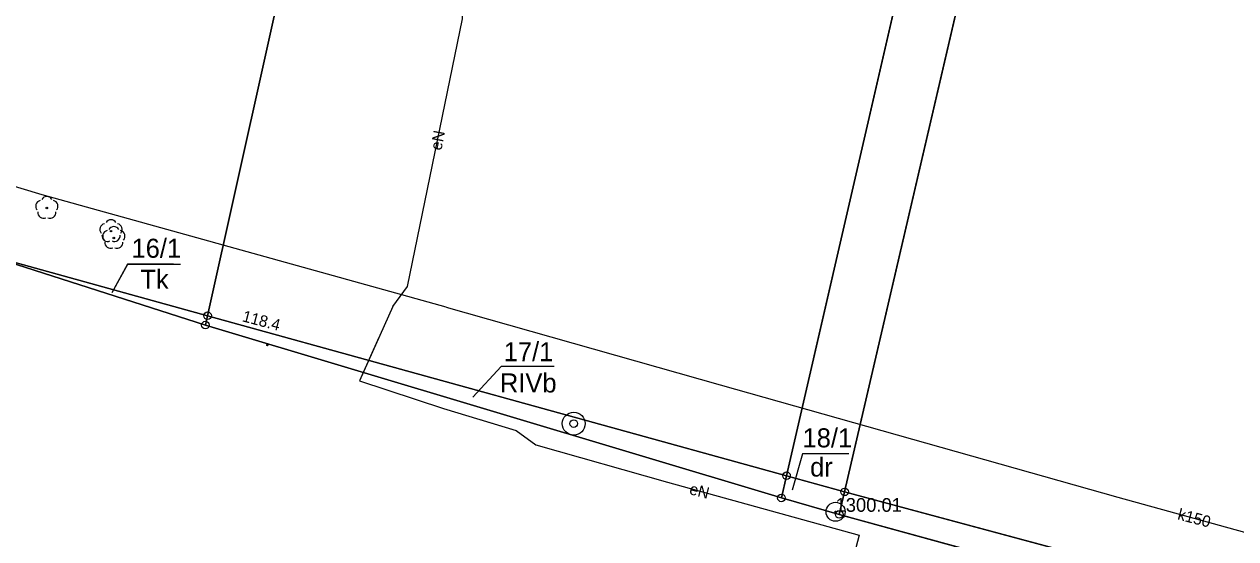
# Model space of a CAD drawing. Extents: x 6424617 to 6425697, y 5665845 to 5667190.
# Drawn here: x 6424782.2 to 6424861.7, y 5666055.5 to 5666089.2 of the extents above; entities that cross this region are included whole.
import ezdxf

# ---------------------------------------------------------------- set-up
doc = ezdxf.new("R2010")
doc.units = 0
for name, color, linetype in [('Warstwa 1', 7, 'Continuous'), ('Warstwa 10', 7, 'Continuous'), ('Warstwa 11', 7, 'Continuous'), ('Warstwa 12', 7, 'Continuous'), ('Warstwa 13', 7, 'Continuous'), ('Warstwa 15', 7, 'Continuous'), ('Warstwa 2', 7, 'Continuous'), ('Warstwa 3', 7, 'Continuous'), ('Warstwa 30', 7, 'Continuous'), ('Warstwa 4', 7, 'Continuous'), ('Warstwa 6', 7, 'Continuous'), ('Warstwa 8', 7, 'Continuous')]:
    doc.layers.add(name, color=color, linetype=linetype)

msp = doc.modelspace()

# ---------------------------------------------------------------- linework, layer by layer
at = {"layer": 'Warstwa 1'}
for p, q in [((6424832.261, 5666059.596), (6424844.483, 5666112.623)), ((6424832.261, 5666059.596), (6424844.483, 5666112.623)), ((6424836.069, 5666058.54), (6424848.434, 5666111.775)), ((6424836.069, 5666058.54), (6424848.434, 5666111.775)), ((6424794.275, 5666070.095), (6424801.04, 5666100.505)), ((6424794.275, 5666070.095), (6424801.04, 5666100.505)), ((6424779.333, 5666074.236), (6424794.275, 5666070.095)), ((6424779.333, 5666074.236), (6424794.275, 5666070.095)), ((6424779.333, 5666074.236), (6424794.137, 5666069.487)), ((6424779.333, 5666074.236), (6424794.137, 5666069.487)), ((6424794.137, 5666069.487), (6424794.275, 5666070.095)), ((6424794.137, 5666069.487), (6424794.275, 5666070.095)), ((6424794.275, 5666070.095), (6424832.261, 5666059.596)), ((6424794.275, 5666070.095), (6424832.261, 5666059.596)), ((6424794.137, 5666069.487), (6424831.924, 5666058.14)), ((6424794.137, 5666069.487), (6424831.924, 5666058.14)), ((6424831.924, 5666058.14), (6424832.261, 5666059.596)), ((6424831.924, 5666058.14), (6424832.261, 5666059.596)), ((6424832.261, 5666059.596), (6424836.069, 5666058.54)), ((6424832.261, 5666059.596), (6424836.069, 5666058.54)), ((6424831.924, 5666058.14), (6424835.721, 5666057.054)), ((6424831.924, 5666058.14), (6424835.721, 5666057.054)), ((6424835.721, 5666057.054), (6424836.069, 5666058.54)), ((6424835.721, 5666057.054), (6424836.069, 5666058.54)), ((6424836.069, 5666058.54), (6424894.579, 5666042.817)), ((6424836.069, 5666058.54), (6424894.579, 5666042.817)), ((6424835.721, 5666057.054), (6424969.125, 5666020.47)), ((6424835.721, 5666057.054), (6424969.125, 5666020.47))]:
    msp.add_line(p, q, dxfattribs=at)
at = {"layer": 'Warstwa 10'}
for centre in [(6424794.275, 5666070.095), (6424794.137, 5666069.487), (6424794.137, 5666069.487), (6424832.261, 5666059.596), (6424836.069, 5666058.54), (6424831.924, 5666058.14), (6424831.924, 5666058.14), (6424835.721, 5666057.054), (6424835.721, 5666057.054)]:
    msp.add_circle(centre, 0.25, dxfattribs=at)
at = {"layer": 'Warstwa 11'}
for centre in [(6424783.729, 5666077.173), (6424787.941, 5666075.652), (6424788.126, 5666075.2)]:
    msp.add_circle(centre, 0.05, dxfattribs=at)
for centre, start, end in [((6424783.729, 5666077.548), 30.14713, 149.85287), ((6424783.372, 5666077.289), 102.14713, 221.85287), ((6424784.086, 5666077.289), 318.14713, 77.85287), ((6424783.509, 5666076.87), 174.14713, 293.85287), ((6424783.949, 5666076.87), 246.14713, 5.85287), ((6424787.941, 5666076.027), 30.14713, 149.85287), ((6424787.584, 5666075.768), 102.14713, 221.85287), ((6424787.769, 5666075.316), 102.14713, 221.85287), ((6424788.126, 5666075.575), 30.14713, 149.85287), ((6424788.298, 5666075.768), 318.14713, 77.85287), ((6424788.483, 5666075.316), 318.14713, 77.85287), ((6424787.721, 5666075.349), 174.14713, 293.85287), ((6424787.906, 5666074.897), 174.14713, 293.85287), ((6424788.161, 5666075.349), 246.14713, 5.85287), ((6424788.346, 5666074.897), 246.14713, 5.85287)]:
    msp.add_arc(centre, 0.375, start, end, dxfattribs=at)
at = {"layer": 'Warstwa 12'}
for points in [[(6424809.935, 5666070.656), (6424783.427, 5666078.025), (6424764.456, 5666083.749), (6424739.613, 5666091.527), (6424715.65, 5666099.074), (6424704.282, 5666102.608), (6424685.892, 5666108.173), (6424678.724, 5666110.413), (6424672.982, 5666122.702), (6424666.592, 5666122.274)], [(6424806.432, 5666070.699), (6424807.399, 5666072.021), (6424811.008, 5666089.581), (6424811.307, 5666096.789)], [(6424806.432, 5666070.699), (6424804.245, 5666065.824), (6424809.759, 5666064.004), (6424814.529, 5666062.559), (6424815.808, 5666061.619), (6424824.451, 5666059.181), (6424837.021, 5666055.705), (6424833.173, 5666041.029), (6424830.852, 5666030.123), (6424832.02, 5666026.17), (6424832.44, 5666024.14), (6424839.63, 5666022.65), (6424842.32, 5666021.91), (6424840.72, 5666014.14), (6424839.536, 5666008.446)], [(6424809.935, 5666070.656), (6424827.909, 5666065.556), (6424854.005, 5666058.199), (6424902.191, 5666044.874)]]:
    msp.add_lwpolyline(points, dxfattribs=at)
at = {"layer": 'Warstwa 13'}
msp.add_circle((6424798.199, 5666068.179), 0.045, dxfattribs=at)
at = {"layer": 'Warstwa 15'}
for points in [[(6424792.041, 5666073.474), (6424789.03, 5666073.474), (6424788.002, 5666071.612)], [(6424816.487, 5666066.764), (6424813.535, 5666066.764), (6424811.681, 5666064.755)], [(6424836.35, 5666061.029), (6424833.3, 5666061.029), (6424832.631, 5666058.648)]]:
    msp.add_lwpolyline(points, dxfattribs=at)
at = {"layer": 'Warstwa 2'}
for points in [[(6424792.503, 5666073.469), (6424789.03, 5666073.469), (6424788.002, 5666071.612)], [(6424817.007, 5666066.758), (6424813.535, 5666066.758), (6424811.681, 5666064.755)], [(6424836.35, 5666061.029), (6424833.3, 5666061.029), (6424832.631, 5666058.648)]]:
    msp.add_lwpolyline(points, dxfattribs=at)
at = {"layer": 'Warstwa 3'}
for radius in [0.625, 0.045]:
    msp.add_circle((6424835.48, 5666057.23), radius, dxfattribs=at)
at = {"layer": 'Warstwa 30'}
for radius in [0.75, 0.25]:
    msp.add_circle((6424818.302, 5666063.018), radius, dxfattribs=at)
at = {"layer": 'Warstwa 6'}
for points in [[(6424854.405, 5666155.706), (6424844.483, 5666112.623), (6424832.261, 5666059.596), (6424836.069, 5666058.54), (6424848.434, 5666111.775), (6424858.372, 5666154.628), (6424860.068, 5666161.718), (6424874.142, 5666220.733), (6424875.3, 5666225.6), (6424883.591, 5666260.362), (6424885.665, 5666269.038), (6424887.972, 5666278.68), (6424890.615, 5666291.389), (6424891.59, 5666295.947), (6424888.255, 5666297.218), (6424884.032, 5666279.588), (6424881.866, 5666269.974)], [(6424995.086, 5666125.706), (6424929.132, 5666143.293), (6424860.068, 5666161.718), (6424858.372, 5666154.628), (6424848.434, 5666111.775), (6424836.069, 5666058.54), (6424900.676, 5666041.179), (6424958.467, 5666024.929), (6424969.493, 5666021.946)], [(6424854.405, 5666155.706), (6424811.635, 5666146.942), (6424805.696, 5666121.432), (6424794.275, 5666070.095), (6424832.261, 5666059.596), (6424844.483, 5666112.623)], [(6424722.032, 5666092.611), (6424752.267, 5666082.904), (6424779.333, 5666074.236), (6424794.275, 5666070.095), (6424805.696, 5666121.432), (6424811.635, 5666146.942), (6424812.055, 5666148.577), (6424731.281, 5666133.882), (6424732.683, 5666141.446), (6424721.939, 5666132.925), (6424730.638, 5666130.29)], [(6424779.333, 5666074.236), (6424794.137, 5666069.487), (6424794.275, 5666070.095)], [(6424831.924, 5666058.14), (6424832.261, 5666059.596), (6424794.275, 5666070.095), (6424794.137, 5666069.487)], [(6424831.924, 5666058.14), (6424835.721, 5666057.054), (6424836.069, 5666058.54), (6424832.261, 5666059.596)], [(6424900.676, 5666041.179), (6424836.069, 5666058.54), (6424835.721, 5666057.054), (6424969.125, 5666020.47), (6424969.493, 5666021.946), (6424958.467, 5666024.929)]]:
    msp.add_lwpolyline(points, close=True, dxfattribs=at)
msp.add_lwpolyline([(6425247.916, 5665916.885), (6425244.899, 5665943.26), (6425213.05, 5665952.08), (6425191.264, 5665958.118), (6425175.276, 5665962.552), (6425160.354, 5665966.672), (6425114.343, 5665979.367), (6425066.833, 5665992.221), (6424969.125, 5666020.47), (6424835.721, 5666057.054), (6424831.924, 5666058.14), (6424794.137, 5666069.487), (6424779.333, 5666074.236), (6424752.267, 5666082.904), (6424722.032, 5666092.611), (6424673.979, 5666108.224), (6424664.196, 5666111.587)], dxfattribs=at)
at = {"layer": 'Warstwa 8'}
msp.add_line((6424805.517, 5666068.66), (6424804.425, 5666066.226), dxfattribs=at)
msp.add_lwpolyline([(6424812.068, 5666063.305), (6424814.529, 5666062.559), (6424814.532, 5666062.557)], dxfattribs=at)

# ---------------------------------------------------------------- texts
at = {"layer": 'Warstwa 13'}
for s, rotation, p in [('eN', 79.07963, (6424809.616, 5666080.914)), ('118.4', 345.24145, (6424796.503, 5666069.741)), ('eN', 345.23572, (6424825.837, 5666058.402)), ('k150', 345.34458, (6424857.87, 5666056.738))]:
    msp.add_text(s, height=0.75, rotation=rotation, dxfattribs=at).set_placement(p)
at = {"layer": 'Warstwa 15'}
for s, p in [('16/1', (6424789.286, 5666073.903)), ('17/1', (6424813.707, 5666067.113)), ('18/1', (6424833.313, 5666061.46))]:
    msp.add_text(s, height=1.25, dxfattribs=at).set_placement(p)
at = {"layer": 'Warstwa 2'}
for s, p in [('Tk', (6424789.864, 5666071.868)), ('RIVb', (6424813.46, 5666065.063)), ('dr', (6424833.808, 5666059.542))]:
    msp.add_text(s, height=1.25, dxfattribs=at).set_placement(p)
at = {"layer": 'Warstwa 4'}
msp.add_text('1300.01', height=0.9, dxfattribs=at).set_placement((6424835.48, 5666057.23))

doc.saveas('drawing.dxf')
